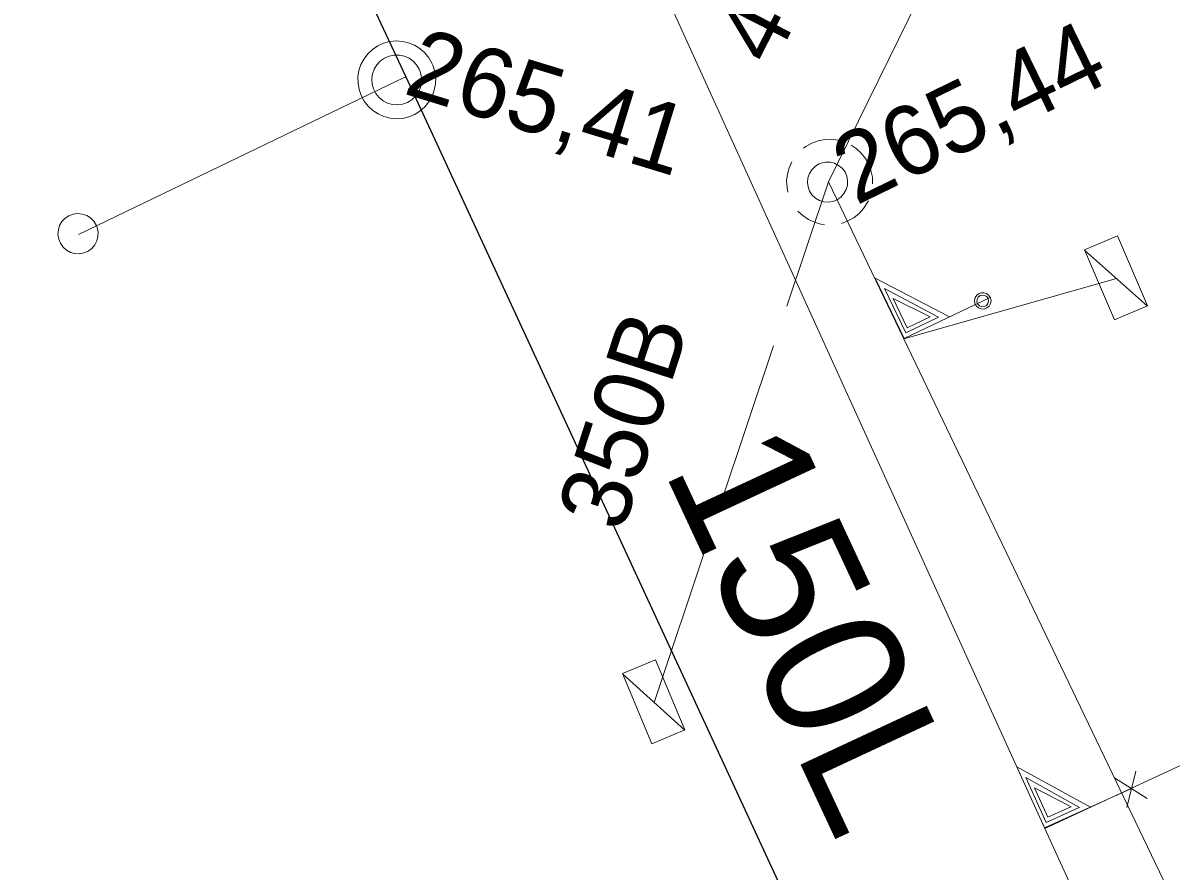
# Model space of a CAD drawing. Extents: x -732096 to -731933, y -1048703 to -1047964.
# Drawn here: x -732047.25 to -732034.06, y -1048482.15 to -1048472.41 of the extents above; entities that cross this region are included whole.
import ezdxf

# ---------------------------------------------------------------- set-up
doc = ezdxf.new("R2010")
doc.units = 0
doc.header["$LTSCALE"] = 0.32
doc.linetypes.add('LONG_DASHED', pattern=[7.5, 6, -1.5])
doc.layers.add('1', color=7, linetype='Continuous')
for name, color, linetype, lineweight in [('18', 7, 'Continuous', 13), ('20', 7, 'Continuous', 13), ('49', 7, 'Continuous', 13), ('8', 7, 'Continuous', 13)]:
    doc.layers.add(name, color=color, linetype=linetype, lineweight=lineweight)

msp = doc.modelspace()

# ---------------------------------------------------------------- linework, layer by layer
at = {"layer": '18'}
for p, q in [((-732035.057, -1048475.016), (-732034.335, -1048475.658)), ((-732040.364, -1048479.883), (-732039.647, -1048480.531)), ((-732034.468, -1048481), (-732034.574, -1048481.417)), ((-732034.339, -1048481.313), (-732034.715, -1048481.076))]:
    msp.add_line(p, q, dxfattribs=at)
for points in [[(-732037.889, -1048473.752), (-732037.965, -1048473.743), (-732038.042, -1048473.745), (-732038.118, -1048473.76), (-732038.19, -1048473.786), (-732038.257, -1048473.824), (-732038.286, -1048473.844)], [(-732037.493, -1048474.253), (-732037.495, -1048474.176), (-732037.511, -1048474.1), (-732037.537, -1048474.029), (-732037.575, -1048473.962), (-732037.623, -1048473.901), (-732037.679, -1048473.848), (-732037.737, -1048473.81)], [(-732038.419, -1048474.001), (-732038.45, -1048474.071), (-732038.47, -1048474.145), (-732038.479, -1048474.221), (-732038.474, -1048474.298), (-732038.466, -1048474.348)], [(-732037.848, -1048474.709), (-732037.776, -1048474.681), (-732037.708, -1048474.643), (-732037.648, -1048474.595), (-732037.597, -1048474.539), (-732037.554, -1048474.474), (-732037.541, -1048474.45)], [(-732038.35, -1048474.568), (-732038.294, -1048474.619), (-732038.23, -1048474.663), (-732038.161, -1048474.696), (-732038.087, -1048474.718), (-732038.046, -1048474.725)], [(-732036.142, -1048475.558), (-732037.129, -1048476.031), (-732037.462, -1048475.337), (-732036.608, -1048475.781)], [(-732036.736, -1048475.787), (-732037.111, -1048475.967), (-732037.356, -1048475.457), (-732036.735, -1048475.787)], [(-732036.832, -1048475.781), (-732037.095, -1048475.908), (-732037.256, -1048475.572), (-732036.832, -1048475.782)], [(-732034.519, -1048481.199), (-732035.516, -1048481.653), (-732035.835, -1048480.952), (-732034.99, -1048481.413)], [(-732035.119, -1048481.417), (-732035.497, -1048481.589), (-732035.731, -1048481.074), (-732035.117, -1048481.416)], [(-732035.214, -1048481.409), (-732035.48, -1048481.53), (-732035.634, -1048481.191), (-732035.213, -1048481.41)]]:
    msp.add_lwpolyline(points, dxfattribs=at)
for points in [[(-732038.109, -1048474.026), (-732038.153, -1048474.054), (-732038.19, -1048474.092), (-732038.218, -1048474.136), (-732038.235, -1048474.186), (-732038.24, -1048474.238), (-732038.233, -1048474.29), (-732038.215, -1048474.339), (-732038.186, -1048474.383), (-732038.147, -1048474.419), (-732038.101, -1048474.446), (-732038.051, -1048474.461), (-732037.999, -1048474.465), (-732037.947, -1048474.456), (-732037.899, -1048474.436), (-732037.855, -1048474.406), (-732037.821, -1048474.367), (-732037.795, -1048474.321), (-732037.781, -1048474.27), (-732037.779, -1048474.218), (-732037.789, -1048474.166), (-732037.809, -1048474.118), (-732037.841, -1048474.076), (-732037.882, -1048474.042), (-732037.929, -1048474.018), (-732037.979, -1048474.006), (-732038.032, -1048474.004), (-732038.083, -1048474.015)], [(-732034.679, -1048474.85), (-732034.336, -1048475.654), (-732034.715, -1048475.816), (-732035.058, -1048475.012)], [(-732036.267, -1048475.514), (-732036.294, -1048475.533), (-732036.313, -1048475.561), (-732036.321, -1048475.594), (-732036.316, -1048475.627), (-732036.301, -1048475.656), (-732036.276, -1048475.679), (-732036.244, -1048475.691), (-732036.211, -1048475.692), (-732036.18, -1048475.68), (-732036.154, -1048475.659), (-732036.137, -1048475.63), (-732036.132, -1048475.596), (-732036.139, -1048475.564), (-732036.156, -1048475.535), (-732036.183, -1048475.514), (-732036.215, -1048475.505), (-732036.248, -1048475.507)], [(-732036.256, -1048475.538), (-732036.279, -1048475.556), (-732036.293, -1048475.58), (-732036.294, -1048475.608), (-732036.284, -1048475.635), (-732036.265, -1048475.655), (-732036.238, -1048475.665), (-732036.21, -1048475.663), (-732036.185, -1048475.65), (-732036.168, -1048475.629), (-732036.161, -1048475.601), (-732036.165, -1048475.573), (-732036.181, -1048475.55), (-732036.206, -1048475.535), (-732036.233, -1048475.532)], [(-732039.985, -1048479.72), (-732039.649, -1048480.527), (-732040.029, -1048480.686), (-732040.365, -1048479.879)]]:
    msp.add_lwpolyline(points, close=True, dxfattribs=at)
at = {"layer": '20'}
for p, q in [((-732038, -1048474.23), (-732035.87, -1048469.9)), ((-732038, -1048474.23), (-732035.87, -1048469.9)), ((-732020.46, -1048510.78), (-732038, -1048474.23)), ((-732020.46, -1048510.78), (-732038, -1048474.23))]:
    msp.add_line(p, q, dxfattribs=at)
at = {"layer": '20', "linetype": 'LONG_DASHED'}
msp.add_line((-732040, -1048480.21), (-732038, -1048474.23), dxfattribs=at)
msp.add_line((-732040, -1048480.21), (-732038, -1048474.23), dxfattribs=at)
at = {"layer": '20'}
msp.add_lwpolyline([(-732034.829, -1048483.16), (-732035.513, -1048481.657), (-732046.05, -1048458.48), (-732047.25, -1048455.84)], dxfattribs=at)
msp.add_lwpolyline([(-732034.829, -1048483.16), (-732035.513, -1048481.657), (-732046.05, -1048458.48), (-732047.25, -1048455.84)], dxfattribs=at)
at = {"layer": '49'}
for p, q in [((-732034.69, -1048475.34), (-732037.134, -1048476.033)), ((-732034.69, -1048475.34), (-732037.134, -1048476.033)), ((-732029.399, -1048478.82), (-732035.513, -1048481.657)), ((-732029.399, -1048478.82), (-732035.513, -1048481.657))]:
    msp.add_line(p, q, dxfattribs=at)
at = {"layer": '8'}
for p, q in [((-732042.953, -1048473.07), (-732046.613, -1048474.837)), ((-732042.854, -1048473.025), (-732042.953, -1048473.07))]:
    msp.add_line(p, q, dxfattribs=at)
at = {"layer": '8', "lineweight": 25}
msp.add_lwpolyline([(-732043.199, -1048472.29), (-732042.854, -1048473.025), (-732034.093, -1048491.956), (-732023.079, -1048515.311), (-732013.932, -1048535.062), (-732012.27, -1048538.65), (-732009.129, -1048546.26)], dxfattribs=at)
at = {"layer": '8'}
for points in [[(-732042.553, -1048472.869), (-732042.589, -1048472.806), (-732042.636, -1048472.749), (-732042.691, -1048472.701), (-732042.753, -1048472.663), (-732042.821, -1048472.634), (-732042.892, -1048472.618), (-732042.964, -1048472.613), (-732043.037, -1048472.62), (-732043.108, -1048472.639), (-732043.175, -1048472.67), (-732043.236, -1048472.711), (-732043.289, -1048472.761), (-732043.333, -1048472.818), (-732043.368, -1048472.883), (-732043.391, -1048472.953), (-732043.403, -1048473.025), (-732043.402, -1048473.099), (-732043.39, -1048473.171), (-732043.366, -1048473.24), (-732043.332, -1048473.304), (-732043.287, -1048473.362), (-732043.233, -1048473.412), (-732043.172, -1048473.452), (-732043.105, -1048473.482), (-732043.034, -1048473.5), (-732042.962, -1048473.507), (-732042.889, -1048473.502), (-732042.817, -1048473.485), (-732042.75, -1048473.457), (-732042.688, -1048473.417), (-732042.633, -1048473.368), (-732042.587, -1048473.311), (-732042.551, -1048473.248), (-732042.526, -1048473.179), (-732042.512, -1048473.107), (-732042.51, -1048473.034), (-732042.521, -1048472.962), (-732042.543, -1048472.892)], [(-732042.698, -1048472.938), (-732042.729, -1048472.888), (-732042.769, -1048472.845), (-732042.816, -1048472.811), (-732042.87, -1048472.788), (-732042.927, -1048472.775), (-732042.985, -1048472.775), (-732043.043, -1048472.787), (-732043.097, -1048472.81), (-732043.144, -1048472.843), (-732043.185, -1048472.887), (-732043.215, -1048472.937), (-732043.235, -1048472.991), (-732043.243, -1048473.049), (-732043.239, -1048473.108), (-732043.224, -1048473.164), (-732043.197, -1048473.217), (-732043.16, -1048473.262), (-732043.115, -1048473.299), (-732043.063, -1048473.326), (-732043.006, -1048473.342), (-732042.948, -1048473.346), (-732042.89, -1048473.338), (-732042.835, -1048473.319), (-732042.785, -1048473.288), (-732042.742, -1048473.249), (-732042.708, -1048473.201), (-732042.685, -1048473.147), (-732042.673, -1048473.091), (-732042.673, -1048473.032), (-732042.684, -1048472.974)], [(-732046.409, -1048474.727), (-732046.436, -1048474.683), (-732046.474, -1048474.646), (-732046.518, -1048474.618), (-732046.569, -1048474.601), (-732046.621, -1048474.596), (-732046.673, -1048474.603), (-732046.722, -1048474.621), (-732046.766, -1048474.65), (-732046.802, -1048474.688), (-732046.829, -1048474.734), (-732046.843, -1048474.784), (-732046.848, -1048474.836), (-732046.839, -1048474.889), (-732046.819, -1048474.937), (-732046.79, -1048474.98), (-732046.75, -1048475.015), (-732046.705, -1048475.041), (-732046.653, -1048475.055), (-732046.601, -1048475.057), (-732046.549, -1048475.047), (-732046.502, -1048475.027), (-732046.459, -1048474.995), (-732046.425, -1048474.955), (-732046.401, -1048474.908), (-732046.389, -1048474.858), (-732046.387, -1048474.805), (-732046.398, -1048474.754)]]:
    msp.add_lwpolyline(points, close=True, dxfattribs=at)

# ---------------------------------------------------------------- texts
at = {"layer": '1'}
for s, height, rotation, p in [('400B', 0.8, 63, (-732038.64, -1048472.925)), ('265,44', 0.8, 26, (-732037.684, -1048474.506)), ('265,41', 0.8, 343, (-732042.897, -1048473.213)), ('350B', 0.8, 72, (-732040.367, -1048478.276)), ('150L', 1.6, 295, (-732039.902, -1048477.531))]:
    msp.add_text(s, height=height, rotation=rotation, dxfattribs=at).set_placement(p)

doc.saveas('drawing.dxf')
